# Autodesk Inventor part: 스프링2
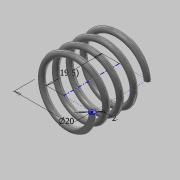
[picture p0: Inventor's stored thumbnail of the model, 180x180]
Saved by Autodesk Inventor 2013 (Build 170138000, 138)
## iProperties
Created: 2016-07
Part Number: 스프링2
Material: 스테인리스강
Document SubType Name: Modeling
Designer: dgall
Density: 8.08 g/cm^3
Mass: 6.25982 g
Surface Area: 15.7247 cm^2
Volume: 0.77473 cm^3
Author: dgall
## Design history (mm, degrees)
sketch "스케치1"
  geometry: L1 (0, 0)-(10, 0); L2 (10, 0)-(10, 19.5); L3 (10, 19.5)-(0, 19.5); L4 (0, 19.5)-(0, 0); C1 r 1 at (10, 0)
  constraints: 8 end point, 2 parallel, 1 centre point, 1 coincident, 1 horizontal, 1 perpendicular
  dimensions: "d0" = 20 diameter of L2 L4; "d2" = 19.5 distance of L3.end L1.start (derived); "d3" = 2 diameter of C1
feature "코일1" pitch "d4" = 10; turns "d6" = 4; dims "d5" = 19.5 (= d2), "d7" = 0, angle "d8" = 90 deg, angle "d9" = 90 deg, "d10" = 0, "d11" = 0
feature "분할1"
node "작업 평면1"
feature "분할2"
node "솔리드1"
